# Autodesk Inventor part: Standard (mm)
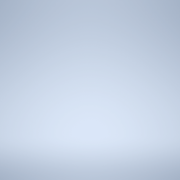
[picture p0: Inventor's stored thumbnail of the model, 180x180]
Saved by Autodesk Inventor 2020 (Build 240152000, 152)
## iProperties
Created: 2019-02
Part Number: Standard (mm)
Material: Ogólny
Document SubType Name: Modeling
Density: 1 g/cm^3
Appearance: Domyślna
Designer: F.Stasiak
Manager: www.cadconsulting.pl
Company: Fabian Stasiak CAD Consulting
Subject: Zbiór ćwiczeń. Autodesk Inventor 2020. Kurs podstawowy
Author: F.Stasiak
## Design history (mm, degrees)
